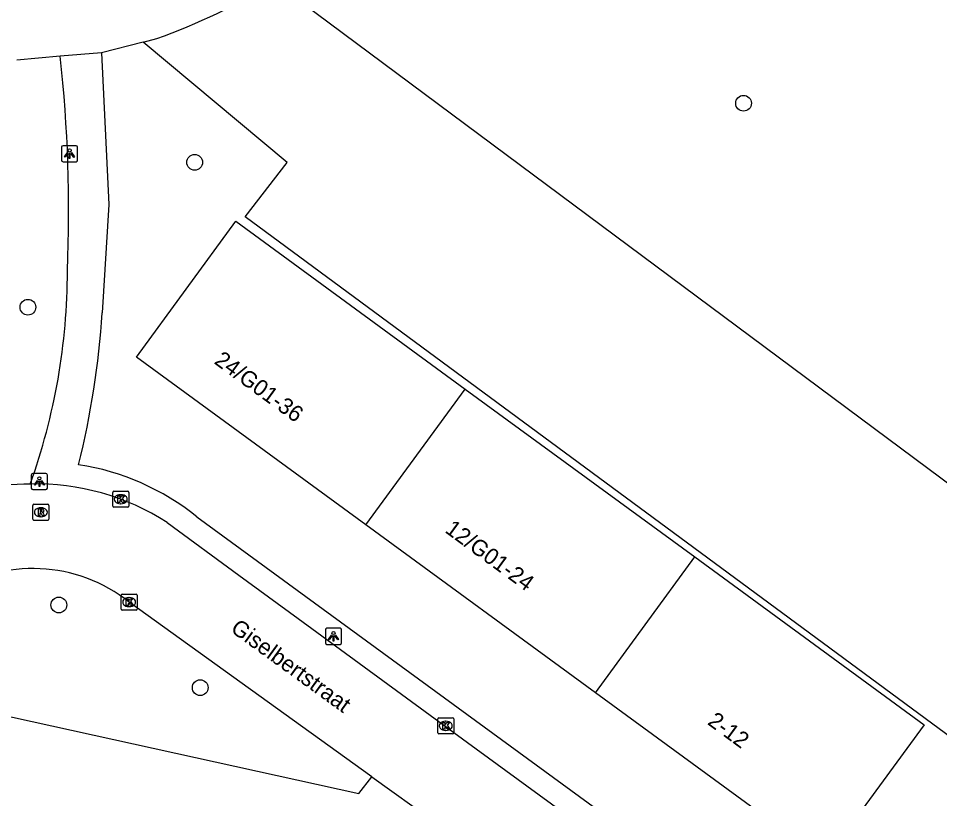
# Model space of a CAD drawing. Extents: x 159675 to 160530, y 382179 to 382901.
# Drawn here: x 160083.4 to 160140.5, y 382273.7 to 382322 of the extents above; entities that cross this region are included whole.
import ezdxf

# ---------------------------------------------------------------- set-up
doc = ezdxf.new("R2010")
doc.units = 0
for name, color, linetype in [('IMGEO_Boom', 7, 'Continuous'), ('IMGEO_Groenvoorziening', 7, 'Continuous'), ('IMGEO_Kolk', 7, 'Continuous'), ('IMGEO_Lichtpunt', 7, 'Continuous'), ('IMGEO_Openbare_ruimte_label', 7, 'Continuous'), ('IMGEO_Pand', 7, 'Continuous'), ('IMGEO_Pand_nummerreeks', 7, 'Continuous'), ('IMGEO_Rijbaan_lokaal_open', 7, 'Continuous'), ('IMGEO_Rioolput', 7, 'Continuous'), ('IMGEO_Voetpad_open', 7, 'Continuous')]:
    doc.layers.add(name, color=color, linetype=linetype)

msp = doc.modelspace()

# ---------------------------------------------------------------- linework, layer by layer
at = {"layer": 'IMGEO_Boom'}
for centre in [(160128.333, 382316.722), (160094.348, 382313.067), (160084.026, 382304.097), (160085.943, 382285.668), (160094.694, 382280.553)]:
    msp.add_circle(centre, 0.489, dxfattribs=at)
at = {"layer": 'IMGEO_Groenvoorziening'}
for points in [[(160099.296, 382324.229), (160154.089, 382283.466)], [(160146.738, 382273.362), (160097.483, 382309.693), (160100.079, 382313.06), (160091.158, 382320.51)], [(160071.119, 382282.18), (160072.654, 382280.295), (160075.37, 382280.425), (160104.517, 382274.01), (160105.327, 382275.04)]]:
    msp.add_lwpolyline(points, dxfattribs=at)
at = {"layer": 'IMGEO_Kolk'}
for p, q in [((160089.275, 382291.788), (160089.275, 382292.64)), ((160089.35, 382292.714), (160090.202, 382292.714)), ((160089.763, 382292.494), (160089.788, 382292.494)), ((160090.276, 382292.64), (160090.276, 382291.788)), ((160090.202, 382291.714), (160089.35, 382291.714)), ((160089.786, 382291.934), (160089.761, 382291.934)), ((160089.793, 382285.419), (160089.793, 382286.271)), ((160089.868, 382286.345), (160090.72, 382286.345)), ((160090.281, 382286.125), (160090.306, 382286.125)), ((160090.794, 382286.271), (160090.794, 382285.419)), ((160090.304, 382285.565), (160090.279, 382285.565)), ((160090.72, 382285.345), (160089.868, 382285.345)), ((160109.395, 382277.762), (160109.395, 382278.614)), ((160109.47, 382278.688), (160110.322, 382278.688)), ((160110.396, 382278.614), (160110.396, 382277.762)), ((160109.883, 382278.468), (160109.908, 382278.468)), ((160110.322, 382277.688), (160109.47, 382277.688)), ((160109.906, 382277.908), (160109.881, 382277.908))]:
    msp.add_line(p, q, dxfattribs=at)
for points in [[(160089.275, 382291.788), (160089.275, 382292.64)], [(160089.35, 382292.714), (160090.202, 382292.714)], [(160089.596, 382292.414), (160089.719, 382292.414), (160089.719, 382292.263), (160089.849, 382292.414), (160090.013, 382292.414), (160089.867, 382292.263), (160090.02, 382292.014), (160089.868, 382292.014), (160089.783, 382292.178), (160089.719, 382292.111), (160089.719, 382292.014), (160089.596, 382292.014), (160089.596, 382292.414)], [(160090.276, 382292.64), (160090.276, 382291.788)], [(160090.202, 382291.714), (160089.35, 382291.714)], [(160089.793, 382285.419), (160089.793, 382286.271)], [(160089.868, 382286.345), (160090.72, 382286.345)], [(160090.114, 382286.045), (160090.237, 382286.045), (160090.237, 382285.894), (160090.367, 382286.045), (160090.531, 382286.045), (160090.385, 382285.894), (160090.538, 382285.645), (160090.386, 382285.645), (160090.301, 382285.809), (160090.237, 382285.742), (160090.237, 382285.645), (160090.114, 382285.645), (160090.114, 382286.045)], [(160090.794, 382286.271), (160090.794, 382285.419)], [(160090.72, 382285.345), (160089.868, 382285.345)], [(160109.395, 382277.762), (160109.395, 382278.614)], [(160109.47, 382278.688), (160110.322, 382278.688)], [(160110.396, 382278.614), (160110.396, 382277.762)], [(160109.716, 382278.388), (160109.839, 382278.388), (160109.839, 382278.237), (160109.969, 382278.388), (160110.133, 382278.388), (160109.987, 382278.237), (160110.14, 382277.988), (160109.988, 382277.988), (160109.903, 382278.152), (160109.839, 382278.085), (160109.839, 382277.988), (160109.716, 382277.988), (160109.716, 382278.388)], [(160110.322, 382277.688), (160109.47, 382277.688)]]:
    msp.add_lwpolyline(points, dxfattribs=at)
for centre, start, end in [((160089.352, 382292.638), 91.552, 178.448), ((160089.352, 382292.638), 91.552, 178.448), ((160090.2, 382292.638), 1.552, 88.448), ((160090.2, 382292.638), 1.552, 88.448), ((160089.352, 382291.79), 181.552, 268.448), ((160089.352, 382291.79), 181.552, 268.448), ((160090.2, 382291.79), 271.552, 358.448), ((160090.2, 382291.79), 271.552, 358.448), ((160089.87, 382286.269), 91.552, 178.448), ((160089.87, 382286.269), 91.552, 178.448), ((160090.718, 382286.269), 1.552, 88.448), ((160090.718, 382286.269), 1.552, 88.448), ((160089.87, 382285.421), 181.552, 268.448), ((160089.87, 382285.421), 181.552, 268.448), ((160090.718, 382285.421), 271.552, 358.448), ((160090.718, 382285.421), 271.552, 358.448), ((160109.472, 382278.612), 91.552, 178.448), ((160109.472, 382278.612), 91.552, 178.448), ((160110.32, 382278.612), 1.552, 88.448), ((160110.32, 382278.612), 1.552, 88.448), ((160109.472, 382277.764), 181.552, 268.448), ((160109.472, 382277.764), 181.552, 268.448), ((160110.32, 382277.764), 271.552, 358.448), ((160110.32, 382277.764), 271.552, 358.448)]:
    msp.add_arc(centre, 0.0765, start, end, dxfattribs=at)
for centre, major_axis, ratio, start_param, end_param in [((160089.762, 382292.214), (-0.387, 0.002), 0.722429, 4.712389, 7.853982), ((160089.787, 382292.214), (-0.39, 0.002), 0.717154, 1.570796, 4.712389), ((160090.28, 382285.845), (-0.387, 0.002), 0.722429, 4.712389, 7.853982), ((160090.305, 382285.845), (-0.39, 0.002), 0.717154, 1.570796, 4.712389), ((160109.882, 382278.188), (-0.387, 0.002), 0.722429, 4.712389, 7.853982), ((160109.907, 382278.188), (-0.39, 0.002), 0.717154, 1.570796, 4.712389)]:
    msp.add_ellipse(centre, major_axis=major_axis, ratio=ratio, start_param=start_param, end_param=end_param, dxfattribs=at)
at = {"layer": 'IMGEO_Lichtpunt'}
for p, q in [((160086.104, 382314.002), (160086.104, 382313.195)), ((160086.104, 382314.002), (160086.104, 382313.195)), ((160087.006, 382314.097), (160086.198, 382314.097)), ((160087.006, 382314.097), (160086.198, 382314.097)), ((160087.1, 382313.195), (160087.1, 382314.002)), ((160087.1, 382313.195), (160087.1, 382314.002)), ((160086.198, 382313.101), (160087.006, 382313.101)), ((160086.198, 382313.101), (160087.006, 382313.101)), ((160084.237, 382293.711), (160084.237, 382292.904)), ((160084.237, 382293.711), (160084.237, 382292.904)), ((160085.139, 382293.806), (160084.331, 382293.806)), ((160085.139, 382293.806), (160084.331, 382293.806)), ((160085.233, 382292.904), (160085.233, 382293.711)), ((160085.233, 382292.904), (160085.233, 382293.711)), ((160084.331, 382292.81), (160085.139, 382292.81)), ((160084.331, 382292.81), (160085.139, 382292.81)), ((160102.447, 382284.133), (160102.447, 382283.326)), ((160102.447, 382284.133), (160102.447, 382283.326)), ((160103.349, 382284.228), (160102.541, 382284.228)), ((160103.349, 382284.228), (160102.541, 382284.228)), ((160103.443, 382283.326), (160103.443, 382284.133)), ((160103.443, 382283.326), (160103.443, 382284.133)), ((160102.541, 382283.232), (160103.349, 382283.232)), ((160102.541, 382283.232), (160103.349, 382283.232))]:
    msp.add_line(p, q, dxfattribs=at)
for points in [[(160086.478, 382313.666), (160086.517, 382313.638), (160086.329, 382313.376), (160086.291, 382313.403), (160086.478, 382313.666)], [(160086.58, 382313.618), (160086.627, 382313.618), (160086.627, 382313.296), (160086.58, 382313.296), (160086.58, 382313.618)], [(160086.69, 382313.638), (160086.728, 382313.665), (160086.915, 382313.403), (160086.876, 382313.375), (160086.69, 382313.638)], [(160084.611, 382293.375), (160084.65, 382293.347), (160084.462, 382293.085), (160084.424, 382293.112), (160084.611, 382293.375)], [(160084.713, 382293.327), (160084.76, 382293.327), (160084.76, 382293.005), (160084.713, 382293.005), (160084.713, 382293.327)], [(160084.823, 382293.347), (160084.861, 382293.374), (160085.048, 382293.112), (160085.009, 382293.084), (160084.823, 382293.347)], [(160102.821, 382283.797), (160102.86, 382283.769), (160102.672, 382283.507), (160102.634, 382283.534), (160102.821, 382283.797)], [(160102.923, 382283.749), (160102.97, 382283.749), (160102.97, 382283.427), (160102.923, 382283.427), (160102.923, 382283.749)], [(160103.033, 382283.769), (160103.071, 382283.796), (160103.258, 382283.534), (160103.219, 382283.506), (160103.033, 382283.769)]]:
    msp.add_lwpolyline(points, dxfattribs=at)
for centre in [(160086.603, 382313.8), (160084.736, 382293.509), (160102.946, 382283.931)]:
    msp.add_circle(centre, 0.0994, dxfattribs=at)
for centre, start, end in [((160086.198, 382314.002), 90, 180), ((160086.198, 382314.002), 90, 180), ((160087.006, 382314.002), 0, 90), ((160087.006, 382314.002), 0, 90), ((160086.198, 382313.195), 180, 270), ((160086.198, 382313.195), 180, 270), ((160087.006, 382313.195), 270, 0), ((160087.006, 382313.195), 270, 360), ((160084.331, 382293.711), 90, 180), ((160084.331, 382293.711), 90, 180), ((160085.139, 382293.711), 0, 90), ((160085.139, 382293.711), 0, 90), ((160084.331, 382292.904), 180, 270), ((160084.331, 382292.904), 180, 270), ((160085.139, 382292.904), 270, 0), ((160085.139, 382292.904), 270, 360), ((160102.541, 382284.133), 90, 180), ((160102.541, 382284.133), 90, 180), ((160103.349, 382284.133), 0, 90), ((160103.349, 382284.133), 0, 90), ((160102.541, 382283.326), 180, 270), ((160102.541, 382283.326), 180, 270), ((160103.349, 382283.326), 270, 0), ((160103.349, 382283.326), 270, 360)]:
    msp.add_arc(centre, 0.0946, start, end, dxfattribs=at)
at = {"layer": 'IMGEO_Pand'}
for points in [[(160104.95, 382290.619), (160090.742, 382301.006), (160096.891, 382309.417), (160111.099, 382299.03)], [(160104.95, 382290.619), (160111.099, 382299.03)], [(160111.099, 382299.03), (160125.307, 382288.642)], [(160119.158, 382280.231), (160104.95, 382290.619)], [(160125.307, 382288.642), (160139.508, 382278.26), (160133.359, 382269.849), (160119.158, 382280.231)], [(160119.158, 382280.231), (160125.307, 382288.642)]]:
    msp.add_lwpolyline(points, dxfattribs=at)
at = {"layer": 'IMGEO_Rijbaan_lokaal_open'}
for points in [[(160092.644, 382290.766), (160097.08, 382287.522), (160100.754, 382284.836), (160111.247, 382277.162), (160114.92, 382274.476), (160122.325, 382269.061), (160125.564, 382266.708), (160129.24, 382264.044), (160131.185, 382262.567)], [(160105.327, 382275.04), (160090.303, 382285.839)], [(160105.327, 382275.04), (160109.176, 382272.273)]]:
    msp.add_lwpolyline(points, dxfattribs=at)
for centre, radius, start, end in [((160084.173, 382280.015), 13.138, 90.0142, 117.8339), ((160084.562, 382278.31), 14.848, 57.0228, 91.5137), ((160084.35, 382278.377), 9.546, 51.4173, 123.3919)]:
    msp.add_arc(centre, radius, start, end, dxfattribs=at)
at = {"layer": 'IMGEO_Rioolput'}
for p, q in [((160084.327, 382290.981), (160084.327, 382291.833)), ((160084.402, 382291.907), (160085.254, 382291.907)), ((160084.815, 382291.687), (160084.84, 382291.687)), ((160085.328, 382291.833), (160085.328, 382290.981)), ((160084.838, 382291.127), (160084.813, 382291.127)), ((160085.254, 382290.907), (160084.402, 382290.907))]:
    msp.add_line(p, q, dxfattribs=at)
for points in [[(160084.327, 382290.981), (160084.327, 382291.833)], [(160084.402, 382291.907), (160085.254, 382291.907)], [(160085.328, 382291.833), (160085.328, 382290.981)], [(160084.916, 382291.605), (160084.664, 382291.607), (160084.664, 382291.207)], [(160084.664, 382291.207), (160084.788, 382291.207), (160084.788, 382291.369), (160084.799, 382291.369)], [(160084.842, 382291.526), (160084.788, 382291.526), (160084.788, 382291.445)], [(160084.788, 382291.445), (160084.84, 382291.445)], [(160084.846, 382291.34), (160084.917, 382291.207), (160085.057, 382291.207), (160084.992, 382291.333)], [(160085.254, 382290.907), (160084.402, 382290.907)]]:
    msp.add_lwpolyline(points, dxfattribs=at)
for centre, radius, start, end in [((160084.404, 382291.831), 0.0765, 91.552, 178.448), ((160084.404, 382291.831), 0.0765, 91.552, 178.448), ((160085.252, 382291.831), 0.0765, 1.552, 88.448), ((160085.252, 382291.831), 0.0765, 1.552, 88.448), ((160084.798, 382291.316), 0.0533, 26.0293, 88.6989), ((160084.824, 382291.634), 0.19, 274.7715, 282.9687), ((160084.848, 382291.43), 0.0964, 77.0061, 93.1865), ((160084.862, 382291.487), 0.0378, 276.6634, 79.6772), ((160084.915, 382291.495), 0.109, 350.3612, 89.416), ((160084.913, 382291.495), 0.112, 277.5842, 350.9817), ((160084.897, 382291.28), 0.108, 29.5134, 73.7905), ((160084.404, 382290.983), 0.0765, 181.552, 268.448), ((160084.404, 382290.983), 0.0765, 181.552, 268.448), ((160085.252, 382290.983), 0.0765, 271.552, 358.448), ((160085.252, 382290.983), 0.0765, 271.552, 358.448)]:
    msp.add_arc(centre, radius, start, end, dxfattribs=at)
for centre, major_axis, ratio, start_param, end_param in [((160084.814, 382291.407), (-0.387, 0.002), 0.722429, 4.712389, 7.853982), ((160084.839, 382291.407), (-0.39, 0.002), 0.717154, 1.570796, 4.712389)]:
    msp.add_ellipse(centre, major_axis=major_axis, ratio=ratio, start_param=start_param, end_param=end_param, dxfattribs=at)
at = {"layer": 'IMGEO_Voetpad_open'}
for points in [[(160091.158, 382320.51), (160088.577, 382319.845)], [(160091.158, 382320.51), (160091.998, 382320.726)], [(160086.028, 382319.631), (160083.339, 382319.397)], [(160088.577, 382319.845), (160086.028, 382319.631)], [(160088.577, 382319.845), (160089.038, 382310.447), (160088.624, 382303.755)], [(160094.492, 382291.126), (160137.034, 382260.024)]]:
    msp.add_lwpolyline(points, dxfattribs=at)
for centre, radius, start, end in [((160079.113, 382356.924), 38.423, 289.5938, 301.6877), ((159998.244, 382310.063), 88.304, 357.59334, 6.22037), ((160047.379, 382306.364), 39.091, 340.2477, 359.987), ((160035.838, 382307.132), 52.894, 346.0146, 356.3393), ((160084.814, 382279.065), 15.464, 51.2577, 81.2606)]:
    msp.add_arc(centre, radius, start, end, dxfattribs=at)

# ---------------------------------------------------------------- texts
at = {"layer": 'IMGEO_Openbare_ruimte_label'}
msp.add_text('Giselbertstraat', height=1, rotation=324.0358, dxfattribs=at).set_placement((160096.51, 382284.062))
at = {"layer": 'IMGEO_Pand_nummerreeks'}
for s, p in [('24/G01-36', (160095.502, 382300.648)), ('12/G01-24', (160109.784, 382290.206)), ('2-12', (160126.043, 382278.319))]:
    msp.add_text(s, height=1, rotation=323.8297, dxfattribs=at).set_placement(p)

doc.saveas('drawing.dxf')
